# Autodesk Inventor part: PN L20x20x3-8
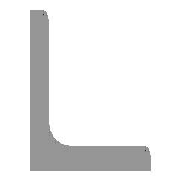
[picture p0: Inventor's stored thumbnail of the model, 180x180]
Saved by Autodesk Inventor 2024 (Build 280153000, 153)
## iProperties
Company: ATC
_CCFamilyMember: 10
_CCFamilyDisplayName: PN EN 10056-1 (Kątownik równoramienny) - Kątownik równoramienny
_FrameMemberDoc: Frame Member File
_Version: 15.0.0
Created: 2023-03
Part Number: PN L20x20x3-8
Material: Ogólny
Description: Kątownik równoramienny
Document SubType Name: Modeling
Standard: PN EN 10056-1
Designer: Andrzej Jaskulski
Standards Organization: PN
Language: pl-PL
Size Designation: L20x20x3
Categories: <MemberInstance><Categories><Category DisplayName="Kształtowniki konstrukcyjne" InternalName="089c4875-fa83-4c05-b084-43b9cc11f5ed" Mnemonic="GRDR"><CategoryPar
Stock Number: L20x20x3
Density: 1 g/cm^3
Appearance: Domyślna
Checked By: A.J.
Engr Approved By: Andrzej Jaskulski
Mfg Approved By: Andrzej Jaskulski
Authority: A.J.
IsCustomPart: 1
G_L: 294,364 mm
G_W: 20,000 mm
G_H: 20,000 mm
+CD916162-73E1-4763-A06B-E43C6B1B9137+CUTDETAIL1: Kąt cięcia 53,58 deg
+931DD53C-35EB-4465-9852-5478F24CB595+CUTDETAIL2: Kąt cięcia 53,58 deg
Author: Andrzej Jaskulski
Title: A.J.: Kurs R2024-MEP
Revision Number: 1/24
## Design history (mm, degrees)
node "Płaszczyzna początkowa"
node "Płaszczyzna końcowa"
sketch "Szkic"
  geometry: L1 (-2.975, 0.525)-(-2.975, 12.275); L2 (-5.975, 14.025)-(-4.725, 14.025); L3 (-5.975, -5.975)-(-5.975, 14.025); L4 (-5.975, -5.975)-(14.025, -5.975); L5 (14.025, -4.725)-(14.025, -5.975); L6 (0.525, -2.975)-(12.275, -2.975); L7 (0, 18.46)-(0, -10.048) reference; L8 (-10.048, 0)-(18.46, 0) reference; A1 r 3.5 centre (0.525, 0.525) between (-2.975, 0.525) and (0.525, -2.975); A2 r 1.75 centre (-4.725, 12.275) between (-2.975, 12.275) and (-4.725, 14.025); A3 r 1.75 centre (12.275, -4.725) between (14.025, -4.725) and (12.275, -2.975); 3 further points
  constraints: 12 end point, 6 point on circle, 6 point on line, 6 tangent, 3 centre point, 3 horizontal, 3 vertical, 1 equal radius
  dimensions: "d4" = 20 distance of L3.start L4.end (= b); "d6" = 20 distance of L3.start L2.start (= b); "d8" = 3 distance of point (14.025, -2.975) L4.end (= ParT); "d10" = 3 distance of L2.start point (-2.975, 14.025) (= ParT); "d17" = 3.5 radius of A1 (= R); "d18" = 1.75 radius of A2 (= R1); "d19" = 5.97509 distance between parallel lines of L8 L4 (= ex); "d20" = 5.97509 distance between parallel lines of L3 L7 (= d19)
extrude "Bryła" new body sketch "Szkic" stored distance "d11" = 294.36421 (= G_L); taper "d12" = 0 deg
node "Driven Length"
  sketch "Sketch3"
    geometry: L1 (0, 0)-(10, 0) reference
    constraints: 2 end point, 1 horizontal
  workplane "Work Plane10"
node "Płaszczyzna konstrukcyjna11"
feature "Podział1"
node "Płaszczyzna konstrukcyjna12"
feature "Podział2"
body "Solid1"
sketch "Sketch4"
  geometry: L1 (-2, 0)-(12, 0) reference; L2 (-2, 294.364)-(12, 294.364) reference
  dimensions: "d24" = 294.36421 distance between parallel lines of L1 L2 (derived)
other parameters: "b" = 20 [user parameter; used in 3 equation terms], "ParT" = 3 [user parameter; used in 3 equation terms], "R" = 3.5 [user parameter; used in 1 equation term], "R1" = 1.75 [user parameter; used in 1 equation term], "G_L" = 294.36421 (= d24) [user parameter; used in 1 equation term], "d7" = 4 (derived), "d9" = 4 (derived), "ex" = 5.97509 (computed from b, ParT) [user parameter; used in 1 equation term], "G_OFFSET_START" = 0 [user parameter; used in 1 equation term], "G_OFFSET_END" = 14.75556 [user parameter; used in 1 equation term], "d21" = 0 (computed from G_OFFSET_START), "d22" = 294.36421 (= G_OFFSET_END + B_L), "B_L" = 279.60866 [user parameter; used in 1 equation term], "d23" = 90 deg
